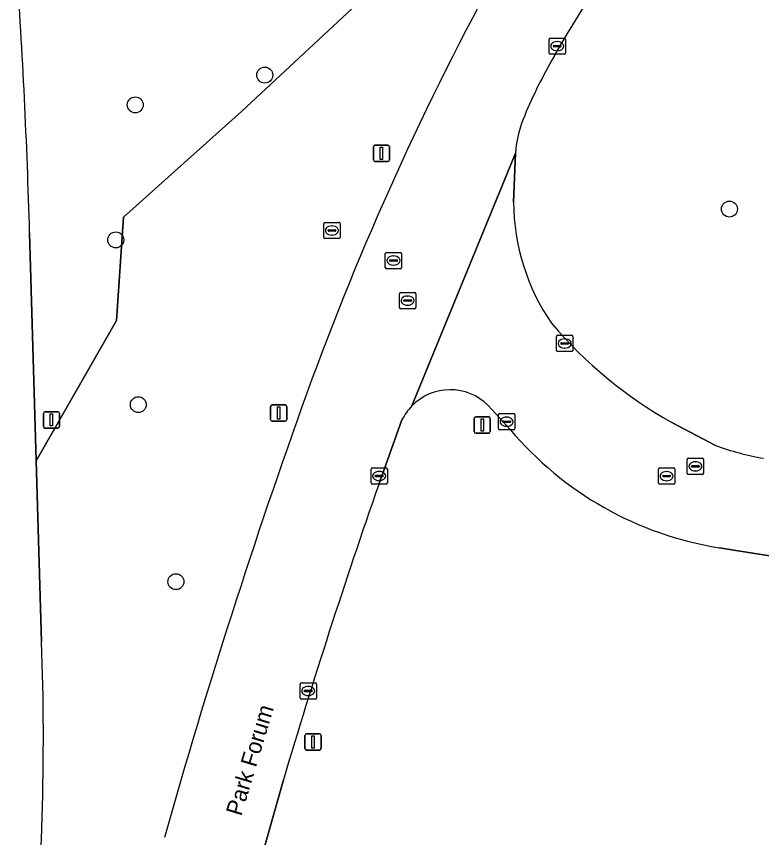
# Model space of a CAD drawing. Extents: x 154324 to 155744, y 382937 to 384188.
# Drawn here: x 155195.7 to 155241.4, y 383378 to 383428.4 of the extents above; entities that cross this region are included whole.
import ezdxf

# ---------------------------------------------------------------- set-up
doc = ezdxf.new("R2010")
doc.units = 0
for name, color, linetype in [('IMGEO_Boom', 7, 'Continuous'), ('IMGEO_Groenvoorziening', 7, 'Continuous'), ('IMGEO_Kolk', 7, 'Continuous'), ('IMGEO_Lichtmast', 7, 'Continuous'), ('IMGEO_Openbare_ruimte_label', 7, 'Continuous'), ('IMGEO_Rijbaan_lokaal_gesloten', 7, 'Continuous'), ('IMGEO_Rijbaan_lokaal_open', 7, 'Continuous'), ('IMGEO_Rijbaan_regionaal_gesloten', 7, 'Continuous'), ('IMGEO_Rioolput', 7, 'Continuous')]:
    doc.layers.add(name, color=color, linetype=linetype)

msp = doc.modelspace()

# ---------------------------------------------------------------- linework, layer by layer
at = {"layer": 'IMGEO_Boom'}
for centre in [(155210.882, 383424.797), (155202.942, 383422.968), (155239.381, 383416.578), (155201.746, 383414.682), (155203.128, 383404.578), (155205.432, 383393.717)]:
    msp.add_circle(centre, 0.489, dxfattribs=at)
at = {"layer": 'IMGEO_Groenvoorziening'}
for points in [[(155196.461, 383415.12), (155196.87, 383401.138), (155201.784, 383409.737), (155202.227, 383416.08), (155209.454, 383422.57), (155218.304, 383430.83), (155232.76, 383449.415), (155225.088, 383476.944)], [(155218.304, 383430.83), (155209.454, 383422.57), (155202.227, 383416.08), (155201.784, 383409.737), (155196.87, 383401.138), (155197.195, 383390.033)], [(155229.103, 383426.799), (155228.606, 383425.92)], [(155226.254, 383420.01), (155226.147, 383416.995)], [(155225.939, 383403.044), (155224.58, 383404.531)], [(155219.297, 383403.636), (155217.88, 383399.681)], [(155235.84, 383403.486), (155238.522, 383402.077)], [(155358.814, 383365.632), (155360.106, 383374.508), (155360.327, 383375.705), (155360.426, 383376.464), (155295.925, 383386.713), (155295.512, 383384.113), (155295.052, 383381.177), (155292.112, 383381.637), (155292.571, 383384.573), (155292.985, 383387.18), (155280.782, 383389.119), (155238.742, 383395.799)], [(155212.028, 383381.558), (155209.577, 383372.88)]]:
    msp.add_lwpolyline(points, dxfattribs=at)
for centre, radius, start, end in [((155301.885, 383383.769), 84.551, 135.8299, 149.4076), ((154803.457, 383404.194), 393.155, 1.59243, 4.00445), ((155387.616, 383342.18), 185.232, 151.172, 160.08181), ((155256.769, 383409.73), 32.485, 150.1067, 157.1969), ((155233.554, 383419.437), 7.323, 156.8139, 175.5108), ((155239.307, 383417.037), 13.16, 180.1821, 214.5883), ((155249.153, 383427.121), 27.126, 220.3266, 240.6076), ((155222.257, 383402.204), 3.288, 45.048, 135.6141), ((155598.09, 383266.96), 408.742, 160.21976, 164.23418), ((155222.261, 383402.202), 3.293, 135.6307, 154.1729), ((155242.084, 383416.64), 21.108, 220.1015, 260.889), ((155244.218, 383417.387), 16.335, 249.5942, 260.2884), ((155581.144, 383272.375), 384.925, 160.68698, 163.52201), ((155039.21, 383384.136), 158.095, 354.33172, 2.13769)]:
    msp.add_arc(centre, radius, start, end, dxfattribs=at)
at = {"layer": 'IMGEO_Kolk'}
for p, q in [((155228.393, 383427.07), (155229.245, 383427.07)), ((155228.318, 383426.144), (155228.318, 383426.996)), ((155228.577, 383426.564), (155228.577, 383426.576)), ((155229.015, 383426.527), (155228.617, 383426.527)), ((155228.62, 383426.613), (155229.018, 383426.613)), ((155228.806, 383426.85), (155228.831, 383426.85)), ((155229.061, 383426.576), (155229.061, 383426.564)), ((155229.319, 383426.996), (155229.319, 383426.144)), ((155229.245, 383426.07), (155228.393, 383426.07)), ((155228.829, 383426.29), (155228.804, 383426.29)), ((155214.499, 383414.836), (155214.499, 383415.688)), ((155214.574, 383415.762), (155215.426, 383415.762)), ((155214.987, 383415.542), (155215.012, 383415.542)), ((155215.5, 383415.688), (155215.5, 383414.836)), ((155214.758, 383415.256), (155214.758, 383415.268)), ((155215.196, 383415.219), (155214.798, 383415.219)), ((155214.801, 383415.305), (155215.199, 383415.305)), ((155215.01, 383414.982), (155214.985, 383414.982)), ((155215.242, 383415.268), (155215.242, 383415.256)), ((155215.426, 383414.762), (155214.574, 383414.762)), ((155228.774, 383407.906), (155228.774, 383408.758)), ((155228.849, 383408.832), (155229.701, 383408.832)), ((155229.076, 383408.375), (155229.474, 383408.375)), ((155229.262, 383408.612), (155229.287, 383408.612)), ((155229.775, 383408.758), (155229.775, 383407.906)), ((155229.033, 383408.326), (155229.033, 383408.338)), ((155229.471, 383408.289), (155229.073, 383408.289)), ((155229.285, 383408.052), (155229.26, 383408.052)), ((155229.517, 383408.338), (155229.517, 383408.326)), ((155229.701, 383407.832), (155228.849, 383407.832)), ((155225.214, 383403.104), (155225.214, 383403.956)), ((155225.289, 383404.03), (155226.141, 383404.03)), ((155226.215, 383403.956), (155226.215, 383403.104)), ((155225.473, 383403.524), (155225.473, 383403.536)), ((155225.911, 383403.487), (155225.513, 383403.487)), ((155225.516, 383403.573), (155225.914, 383403.573)), ((155225.702, 383403.81), (155225.727, 383403.81)), ((155225.957, 383403.536), (155225.957, 383403.524)), ((155226.141, 383403.03), (155225.289, 383403.03)), ((155225.725, 383403.25), (155225.7, 383403.25)), ((155217.399, 383399.775), (155217.399, 383400.627)), ((155217.474, 383400.701), (155218.326, 383400.701)), ((155217.887, 383400.481), (155217.912, 383400.481)), ((155218.4, 383400.627), (155218.4, 383399.775)), ((155217.658, 383400.195), (155217.658, 383400.207)), ((155218.096, 383400.158), (155217.698, 383400.158)), ((155217.701, 383400.244), (155218.099, 383400.244)), ((155217.91, 383399.921), (155217.885, 383399.921)), ((155218.142, 383400.207), (155218.142, 383400.195)), ((155218.326, 383399.701), (155217.474, 383399.701)), ((155213.049, 383386.586), (155213.049, 383387.438)), ((155213.124, 383387.512), (155213.976, 383387.512)), ((155213.537, 383387.292), (155213.562, 383387.292)), ((155214.05, 383387.438), (155214.05, 383386.586)), ((155213.308, 383387.006), (155213.308, 383387.018)), ((155213.746, 383386.969), (155213.348, 383386.969)), ((155213.351, 383387.055), (155213.749, 383387.055)), ((155213.56, 383386.732), (155213.535, 383386.732)), ((155213.792, 383387.018), (155213.792, 383387.006)), ((155213.976, 383386.512), (155213.124, 383386.512))]:
    msp.add_line(p, q, dxfattribs=at)
for points in [[(155228.393, 383427.07), (155229.245, 383427.07)], [(155228.318, 383426.144), (155228.318, 383426.996)], [(155229.319, 383426.996), (155229.319, 383426.144)], [(155229.245, 383426.07), (155228.393, 383426.07)], [(155214.499, 383414.836), (155214.499, 383415.688)], [(155214.574, 383415.762), (155215.426, 383415.762)], [(155215.5, 383415.688), (155215.5, 383414.836)], [(155215.426, 383414.762), (155214.574, 383414.762)], [(155228.774, 383407.906), (155228.774, 383408.758)], [(155228.849, 383408.832), (155229.701, 383408.832)], [(155229.775, 383408.758), (155229.775, 383407.906)], [(155229.701, 383407.832), (155228.849, 383407.832)], [(155225.214, 383403.104), (155225.214, 383403.956)], [(155225.289, 383404.03), (155226.141, 383404.03)], [(155226.215, 383403.956), (155226.215, 383403.104)], [(155226.141, 383403.03), (155225.289, 383403.03)], [(155217.399, 383399.775), (155217.399, 383400.627)], [(155217.474, 383400.701), (155218.326, 383400.701)], [(155218.4, 383400.627), (155218.4, 383399.775)], [(155218.326, 383399.701), (155217.474, 383399.701)], [(155213.049, 383386.586), (155213.049, 383387.438)], [(155213.124, 383387.512), (155213.976, 383387.512)], [(155214.05, 383387.438), (155214.05, 383386.586)], [(155213.976, 383386.512), (155213.124, 383386.512)]]:
    msp.add_lwpolyline(points, dxfattribs=at)
for centre, radius, start, end in [((155228.395, 383426.994), 0.0765, 91.552, 178.448), ((155228.395, 383426.994), 0.0765, 91.552, 178.448), ((155229.243, 383426.994), 0.0765, 1.552, 88.448), ((155229.243, 383426.994), 0.0765, 1.552, 88.448), ((155228.617, 383426.573), 0.0403, 85.8775, 175.7526), ((155228.614, 383426.563), 0.0366, 178.938, 274.7102), ((155229.018, 383426.57), 0.043, 264.8664, 352.4533), ((155229.022, 383426.575), 0.0386, 1.7309, 96.639), ((155228.395, 383426.146), 0.0765, 181.552, 268.448), ((155228.395, 383426.146), 0.0765, 181.552, 268.448), ((155229.243, 383426.146), 0.0765, 271.552, 358.448), ((155229.243, 383426.146), 0.0765, 271.552, 358.448), ((155214.576, 383415.686), 0.0765, 91.552, 178.448), ((155214.576, 383415.686), 0.0765, 91.552, 178.448), ((155215.424, 383415.686), 0.0765, 1.552, 88.448), ((155215.424, 383415.686), 0.0765, 1.552, 88.448), ((155214.798, 383415.265), 0.0403, 85.8775, 175.7526), ((155214.795, 383415.255), 0.0366, 178.938, 274.7102), ((155215.199, 383415.262), 0.043, 264.8664, 352.4533), ((155215.203, 383415.267), 0.0386, 1.7309, 96.639), ((155214.576, 383414.838), 0.0765, 181.552, 268.448), ((155214.576, 383414.838), 0.0765, 181.552, 268.448), ((155215.424, 383414.838), 0.0765, 271.552, 358.448), ((155215.424, 383414.838), 0.0765, 271.552, 358.448), ((155228.851, 383408.756), 0.0765, 91.552, 178.448), ((155228.851, 383408.756), 0.0765, 91.552, 178.448), ((155229.073, 383408.335), 0.0403, 85.8775, 175.7526), ((155229.478, 383408.337), 0.0386, 1.7309, 96.639), ((155229.699, 383408.756), 0.0765, 1.552, 88.448), ((155229.699, 383408.756), 0.0765, 1.552, 88.448), ((155228.851, 383407.908), 0.0765, 181.552, 268.448), ((155228.851, 383407.908), 0.0765, 181.552, 268.448), ((155229.07, 383408.325), 0.0366, 178.938, 274.7102), ((155229.474, 383408.332), 0.043, 264.8664, 352.4533), ((155229.699, 383407.908), 0.0765, 271.552, 358.448), ((155229.699, 383407.908), 0.0765, 271.552, 358.448), ((155225.291, 383403.954), 0.0765, 91.552, 178.448), ((155225.291, 383403.954), 0.0765, 91.552, 178.448), ((155226.139, 383403.954), 0.0765, 1.552, 88.448), ((155226.139, 383403.954), 0.0765, 1.552, 88.448), ((155225.513, 383403.533), 0.0403, 85.8775, 175.7526), ((155225.51, 383403.523), 0.0366, 178.938, 274.7102), ((155225.914, 383403.53), 0.043, 264.8664, 352.4533), ((155225.918, 383403.535), 0.0386, 1.7309, 96.639), ((155225.291, 383403.106), 0.0765, 181.552, 268.448), ((155225.291, 383403.106), 0.0765, 181.552, 268.448), ((155226.139, 383403.106), 0.0765, 271.552, 358.448), ((155226.139, 383403.106), 0.0765, 271.552, 358.448), ((155217.476, 383400.625), 0.0765, 91.552, 178.448), ((155217.476, 383400.625), 0.0765, 91.552, 178.448), ((155218.324, 383400.625), 0.0765, 1.552, 88.448), ((155218.324, 383400.625), 0.0765, 1.552, 88.448), ((155217.698, 383400.204), 0.0403, 85.8775, 175.7526), ((155217.695, 383400.194), 0.0366, 178.938, 274.7102), ((155218.099, 383400.201), 0.043, 264.8664, 352.4533), ((155218.103, 383400.206), 0.0386, 1.7309, 96.639), ((155217.476, 383399.777), 0.0765, 181.552, 268.448), ((155217.476, 383399.777), 0.0765, 181.552, 268.448), ((155218.324, 383399.777), 0.0765, 271.552, 358.448), ((155218.324, 383399.777), 0.0765, 271.552, 358.448), ((155213.126, 383387.436), 0.0765, 91.552, 178.448), ((155213.126, 383387.436), 0.0765, 91.552, 178.448), ((155213.974, 383387.436), 0.0765, 1.552, 88.448), ((155213.974, 383387.436), 0.0765, 1.552, 88.448), ((155213.348, 383387.015), 0.0403, 85.8775, 175.7526), ((155213.345, 383387.005), 0.0366, 178.938, 274.7102), ((155213.749, 383387.012), 0.043, 264.8664, 352.4533), ((155213.753, 383387.017), 0.0386, 1.7309, 96.639), ((155213.126, 383386.588), 0.0765, 181.552, 268.448), ((155213.126, 383386.588), 0.0765, 181.552, 268.448), ((155213.974, 383386.588), 0.0765, 271.552, 358.448), ((155213.974, 383386.588), 0.0765, 271.552, 358.448)]:
    msp.add_arc(centre, radius, start, end, dxfattribs=at)
for centre, major_axis, ratio, start_param, end_param in [((155228.805, 383426.57), (-0.387, 0.002), 0.722429, 4.712389, 7.853982), ((155228.83, 383426.57), (-0.39, 0.002), 0.717154, 1.570796, 4.712389), ((155214.986, 383415.262), (-0.387, 0.002), 0.722429, 4.712389, 7.853982), ((155215.011, 383415.262), (-0.39, 0.002), 0.717154, 1.570796, 4.712389), ((155229.261, 383408.332), (-0.387, 0.002), 0.722429, 4.712389, 7.853982), ((155229.286, 383408.332), (-0.39, 0.002), 0.717154, 1.570796, 4.712389), ((155225.701, 383403.53), (-0.387, 0.002), 0.722429, 4.712389, 7.853982), ((155225.726, 383403.53), (-0.39, 0.002), 0.717154, 1.570796, 4.712389), ((155217.886, 383400.201), (-0.387, 0.002), 0.722429, 4.712389, 7.853982), ((155217.911, 383400.201), (-0.39, 0.002), 0.717154, 1.570796, 4.712389), ((155213.536, 383387.012), (-0.387, 0.002), 0.722429, 4.712389, 7.853982), ((155213.561, 383387.012), (-0.39, 0.002), 0.717154, 1.570796, 4.712389)]:
    msp.add_ellipse(centre, major_axis=major_axis, ratio=ratio, start_param=start_param, end_param=end_param, dxfattribs=at)
at = {"layer": 'IMGEO_Lichtmast'}
for p, q in [((155217.642, 383420.489), (155218.432, 383420.489)), ((155218.432, 383420.489), (155217.642, 383420.489)), ((155217.542, 383419.589), (155217.542, 383420.389)), ((155217.542, 383420.389), (155217.542, 383419.589)), ((155218.532, 383420.389), (155218.532, 383419.589)), ((155218.532, 383419.589), (155218.532, 383420.389)), ((155218.432, 383419.489), (155217.642, 383419.489)), ((155217.642, 383419.489), (155218.432, 383419.489)), ((155211.237, 383403.661), (155211.237, 383404.461)), ((155211.237, 383404.461), (155211.237, 383403.661)), ((155211.337, 383404.561), (155212.127, 383404.561)), ((155212.127, 383404.561), (155211.337, 383404.561)), ((155212.227, 383404.461), (155212.227, 383403.661)), ((155212.227, 383403.661), (155212.227, 383404.461)), ((155197.305, 383403.243), (155197.305, 383404.043)), ((155197.305, 383404.043), (155197.305, 383403.243)), ((155197.405, 383404.143), (155198.195, 383404.143)), ((155198.195, 383404.143), (155197.405, 383404.143)), ((155198.295, 383404.043), (155198.295, 383403.243)), ((155198.295, 383403.243), (155198.295, 383404.043)), ((155212.127, 383403.561), (155211.337, 383403.561)), ((155211.337, 383403.561), (155212.127, 383403.561)), ((155223.726, 383402.926), (155223.726, 383403.726)), ((155223.726, 383403.726), (155223.726, 383402.926)), ((155223.826, 383403.826), (155224.616, 383403.826)), ((155224.616, 383403.826), (155223.826, 383403.826)), ((155224.716, 383403.726), (155224.716, 383402.926)), ((155224.716, 383402.926), (155224.716, 383403.726)), ((155198.195, 383403.143), (155197.405, 383403.143)), ((155197.405, 383403.143), (155198.195, 383403.143)), ((155224.616, 383402.826), (155223.826, 383402.826)), ((155223.826, 383402.826), (155224.616, 383402.826)), ((155213.342, 383383.486), (155213.342, 383384.286)), ((155213.342, 383384.286), (155213.342, 383383.486)), ((155213.442, 383384.386), (155214.232, 383384.386)), ((155214.232, 383384.386), (155213.442, 383384.386)), ((155214.332, 383384.286), (155214.332, 383383.486)), ((155214.332, 383383.486), (155214.332, 383384.286)), ((155214.232, 383383.386), (155213.442, 383383.386)), ((155213.442, 383383.386), (155214.232, 383383.386))]:
    msp.add_line(p, q, dxfattribs=at)
for points in [[(155217.962, 383420.364), (155218.112, 383420.364), (155218.112, 383419.614), (155217.962, 383419.614), (155217.962, 383420.364)], [(155211.657, 383404.436), (155211.807, 383404.436), (155211.807, 383403.686), (155211.657, 383403.686), (155211.657, 383404.436)], [(155197.725, 383404.018), (155197.875, 383404.018), (155197.875, 383403.268), (155197.725, 383403.268), (155197.725, 383404.018)], [(155224.146, 383403.701), (155224.296, 383403.701), (155224.296, 383402.951), (155224.146, 383402.951), (155224.146, 383403.701)], [(155213.762, 383384.261), (155213.912, 383384.261), (155213.912, 383383.511), (155213.762, 383383.511), (155213.762, 383384.261)]]:
    msp.add_lwpolyline(points, dxfattribs=at)
for centre, start, end in [((155217.642, 383420.389), 90, 180), ((155217.642, 383420.389), 90, 180), ((155218.432, 383420.389), 0, 90), ((155218.432, 383420.389), 360, 90), ((155217.642, 383419.589), 180, 270), ((155217.642, 383419.589), 180, 270), ((155218.432, 383419.589), 270, 0), ((155218.432, 383419.589), 270, 0), ((155211.337, 383404.461), 90, 180), ((155211.337, 383404.461), 90, 180), ((155212.127, 383404.461), 0, 90), ((155212.127, 383404.461), 360, 90), ((155197.405, 383404.043), 90, 180), ((155197.405, 383404.043), 90, 180), ((155198.195, 383404.043), 0, 90), ((155198.195, 383404.043), 360, 90), ((155211.337, 383403.661), 180, 270), ((155211.337, 383403.661), 180, 270), ((155212.127, 383403.661), 270, 0), ((155212.127, 383403.661), 270, 0), ((155223.826, 383403.726), 90, 180), ((155223.826, 383403.726), 90, 180), ((155224.616, 383403.726), 0, 90), ((155224.616, 383403.726), 360, 90), ((155197.405, 383403.243), 180, 270), ((155197.405, 383403.243), 180, 270), ((155198.195, 383403.243), 270, 0), ((155198.195, 383403.243), 270, 0), ((155223.826, 383402.926), 180, 270), ((155223.826, 383402.926), 180, 270), ((155224.616, 383402.926), 270, 0), ((155224.616, 383402.926), 270, 0), ((155213.442, 383384.286), 90, 180), ((155213.442, 383384.286), 90, 180), ((155214.232, 383384.286), 0, 90), ((155214.232, 383384.286), 360, 90), ((155213.442, 383383.486), 180, 270), ((155213.442, 383383.486), 180, 270), ((155214.232, 383383.486), 270, 0), ((155214.232, 383383.486), 270, 0)]:
    msp.add_arc(centre, 0.1, start, end, dxfattribs=at)
at = {"layer": 'IMGEO_Rijbaan_lokaal_gesloten'}
for points in [[(155226.147, 383416.995), (155226.254, 383420.01), (155219.907, 383404.504)], [(155224.58, 383404.531), (155225.939, 383403.044)], [(155238.522, 383402.077), (155235.84, 383403.486)], [(155238.742, 383395.799), (155280.782, 383389.119), (155292.985, 383387.18), (155295.925, 383386.713), (155360.426, 383376.464), (155366.366, 383375.502), (155368.377, 383375.447), (155369.374, 383375.593), (155371.331, 383376.087), (155374.899, 383377.537), (155376.703, 383378.478), (155378.429, 383379.542)]]:
    msp.add_lwpolyline(points, dxfattribs=at)
for centre, radius, start, end in [((155239.307, 383417.037), 13.16, 180.1821, 214.5883), ((155249.153, 383427.121), 27.126, 220.3266, 240.6076), ((155222.257, 383402.204), 3.288, 45.048, 135.6141), ((155242.084, 383416.64), 21.108, 220.1015, 260.889), ((155244.218, 383417.387), 16.335, 249.5942, 260.2884)]:
    msp.add_arc(centre, radius, start, end, dxfattribs=at)
at = {"layer": 'IMGEO_Rijbaan_lokaal_open'}
for points in [[(155228.606, 383425.92), (155229.103, 383426.799)], [(155219.907, 383404.504), (155226.254, 383420.01)], [(155217.88, 383399.681), (155219.297, 383403.636)], [(155209.577, 383372.88), (155212.028, 383381.558)]]:
    msp.add_lwpolyline(points, dxfattribs=at)
for centre, radius, start, end in [((155301.885, 383383.769), 84.551, 135.8299, 149.4076), ((155387.616, 383342.18), 185.232, 151.172, 160.08181), ((155256.769, 383409.73), 32.485, 150.1067, 157.1969), ((155233.554, 383419.437), 7.323, 156.8139, 175.5108), ((155598.09, 383266.96), 408.742, 160.21976, 164.23418), ((155222.261, 383402.202), 3.293, 135.6307, 154.1729), ((155581.144, 383272.375), 384.925, 160.68698, 163.52201)]:
    msp.add_arc(centre, radius, start, end, dxfattribs=at)
at = {"layer": 'IMGEO_Rijbaan_regionaal_gesloten'}
msp.add_lwpolyline([(155197.195, 383390.033), (155196.87, 383401.138), (155196.461, 383415.12)], dxfattribs=at)
for centre, radius, start, end in [((154803.457, 383404.194), 393.155, 1.59243, 4.00445), ((155039.21, 383384.136), 158.095, 354.33172, 2.13769)]:
    msp.add_arc(centre, radius, start, end, dxfattribs=at)
at = {"layer": 'IMGEO_Rioolput'}
for p, q in [((155218.35, 383413.918), (155219.202, 383413.918)), ((155218.275, 383412.992), (155218.275, 383413.844)), ((155218.534, 383413.412), (155218.534, 383413.424)), ((155218.577, 383413.461), (155218.975, 383413.461)), ((155218.763, 383413.698), (155218.788, 383413.698)), ((155219.018, 383413.424), (155219.018, 383413.412)), ((155219.276, 383413.844), (155219.276, 383412.992)), ((155219.202, 383412.918), (155218.35, 383412.918)), ((155218.972, 383413.375), (155218.574, 383413.375)), ((155218.786, 383413.138), (155218.761, 383413.138)), ((155219.22, 383411.459), (155220.072, 383411.459)), ((155219.145, 383410.533), (155219.145, 383411.385)), ((155219.404, 383410.953), (155219.404, 383410.965)), ((155219.842, 383410.916), (155219.444, 383410.916)), ((155219.447, 383411.002), (155219.845, 383411.002)), ((155219.633, 383411.239), (155219.658, 383411.239)), ((155219.888, 383410.965), (155219.888, 383410.953)), ((155220.146, 383411.385), (155220.146, 383410.533)), ((155220.072, 383410.459), (155219.22, 383410.459)), ((155219.656, 383410.679), (155219.631, 383410.679)), ((155236.791, 383400.368), (155236.791, 383401.22)), ((155236.866, 383401.294), (155237.718, 383401.294)), ((155237.093, 383400.837), (155237.491, 383400.837)), ((155237.279, 383401.074), (155237.304, 383401.074)), ((155237.792, 383401.22), (155237.792, 383400.368)), ((155235.026, 383399.767), (155235.026, 383400.619)), ((155235.101, 383400.693), (155235.953, 383400.693)), ((155235.514, 383400.473), (155235.539, 383400.473)), ((155236.027, 383400.619), (155236.027, 383399.767)), ((155237.05, 383400.788), (155237.05, 383400.8)), ((155237.488, 383400.751), (155237.09, 383400.751)), ((155237.302, 383400.514), (155237.277, 383400.514)), ((155237.534, 383400.8), (155237.534, 383400.788)), ((155235.285, 383400.187), (155235.285, 383400.199)), ((155235.723, 383400.15), (155235.325, 383400.15)), ((155235.328, 383400.236), (155235.726, 383400.236)), ((155235.537, 383399.913), (155235.512, 383399.913)), ((155235.769, 383400.199), (155235.769, 383400.187)), ((155237.718, 383400.294), (155236.866, 383400.294)), ((155235.953, 383399.693), (155235.101, 383399.693))]:
    msp.add_line(p, q, dxfattribs=at)
for points in [[(155218.35, 383413.918), (155219.202, 383413.918)], [(155218.275, 383412.992), (155218.275, 383413.844)], [(155219.276, 383413.844), (155219.276, 383412.992)], [(155219.202, 383412.918), (155218.35, 383412.918)], [(155219.22, 383411.459), (155220.072, 383411.459)], [(155219.145, 383410.533), (155219.145, 383411.385)], [(155220.146, 383411.385), (155220.146, 383410.533)], [(155220.072, 383410.459), (155219.22, 383410.459)], [(155236.791, 383400.368), (155236.791, 383401.22)], [(155236.866, 383401.294), (155237.718, 383401.294)], [(155237.792, 383401.22), (155237.792, 383400.368)], [(155235.026, 383399.767), (155235.026, 383400.619)], [(155235.101, 383400.693), (155235.953, 383400.693)], [(155236.027, 383400.619), (155236.027, 383399.767)], [(155237.718, 383400.294), (155236.866, 383400.294)], [(155235.953, 383399.693), (155235.101, 383399.693)]]:
    msp.add_lwpolyline(points, dxfattribs=at)
for centre, radius, start, end in [((155218.352, 383413.842), 0.0765, 91.552, 178.448), ((155218.352, 383413.842), 0.0765, 91.552, 178.448), ((155219.2, 383413.842), 0.0765, 1.552, 88.448), ((155219.2, 383413.842), 0.0765, 1.552, 88.448), ((155218.574, 383413.421), 0.0403, 85.8775, 175.7526), ((155218.571, 383413.411), 0.0366, 178.938, 274.7102), ((155218.975, 383413.418), 0.043, 264.8664, 352.4533), ((155218.979, 383413.423), 0.0386, 1.7309, 96.639), ((155218.352, 383412.994), 0.0765, 181.552, 268.448), ((155218.352, 383412.994), 0.0765, 181.552, 268.448), ((155219.2, 383412.994), 0.0765, 271.552, 358.448), ((155219.2, 383412.994), 0.0765, 271.552, 358.448), ((155219.222, 383411.383), 0.0765, 91.552, 178.448), ((155219.222, 383411.383), 0.0765, 91.552, 178.448), ((155220.07, 383411.383), 0.0765, 1.552, 88.448), ((155220.07, 383411.383), 0.0765, 1.552, 88.448), ((155219.444, 383410.962), 0.0403, 85.8775, 175.7526), ((155219.441, 383410.952), 0.0366, 178.938, 274.7102), ((155219.845, 383410.959), 0.043, 264.8664, 352.4533), ((155219.849, 383410.964), 0.0386, 1.7309, 96.639), ((155219.222, 383410.535), 0.0765, 181.552, 268.448), ((155219.222, 383410.535), 0.0765, 181.552, 268.448), ((155220.07, 383410.535), 0.0765, 271.552, 358.448), ((155220.07, 383410.535), 0.0765, 271.552, 358.448), ((155236.868, 383401.218), 0.0765, 91.552, 178.448), ((155236.868, 383401.218), 0.0765, 91.552, 178.448), ((155237.09, 383400.797), 0.0403, 85.8775, 175.7526), ((155237.495, 383400.799), 0.0386, 1.7309, 96.639), ((155237.716, 383401.218), 0.0765, 1.552, 88.448), ((155237.716, 383401.218), 0.0765, 1.552, 88.448), ((155235.103, 383400.617), 0.0765, 91.552, 178.448), ((155235.103, 383400.617), 0.0765, 91.552, 178.448), ((155235.951, 383400.617), 0.0765, 1.552, 88.448), ((155235.951, 383400.617), 0.0765, 1.552, 88.448), ((155236.868, 383400.37), 0.0765, 181.552, 268.448), ((155236.868, 383400.37), 0.0765, 181.552, 268.448), ((155237.087, 383400.787), 0.0366, 178.938, 274.7102), ((155237.491, 383400.794), 0.043, 264.8664, 352.4533), ((155237.716, 383400.37), 0.0765, 271.552, 358.448), ((155237.716, 383400.37), 0.0765, 271.552, 358.448), ((155235.325, 383400.196), 0.0403, 85.8775, 175.7526), ((155235.322, 383400.186), 0.0366, 178.938, 274.7102), ((155235.726, 383400.193), 0.043, 264.8664, 352.4533), ((155235.73, 383400.198), 0.0386, 1.7309, 96.639), ((155235.103, 383399.769), 0.0765, 181.552, 268.448), ((155235.103, 383399.769), 0.0765, 181.552, 268.448), ((155235.951, 383399.769), 0.0765, 271.552, 358.448), ((155235.951, 383399.769), 0.0765, 271.552, 358.448)]:
    msp.add_arc(centre, radius, start, end, dxfattribs=at)
for centre, major_axis, ratio, start_param, end_param in [((155218.762, 383413.418), (-0.387, 0.002), 0.722429, 4.712389, 7.853982), ((155218.787, 383413.418), (-0.39, 0.002), 0.717154, 1.570796, 4.712389), ((155219.632, 383410.959), (-0.387, 0.002), 0.722429, 4.712389, 7.853982), ((155219.657, 383410.959), (-0.39, 0.002), 0.717154, 1.570796, 4.712389), ((155237.278, 383400.794), (-0.387, 0.002), 0.722429, 4.712389, 7.853982), ((155237.303, 383400.794), (-0.39, 0.002), 0.717154, 1.570796, 4.712389), ((155235.513, 383400.193), (-0.387, 0.002), 0.722429, 4.712389, 7.853982), ((155235.538, 383400.193), (-0.39, 0.002), 0.717154, 1.570796, 4.712389)]:
    msp.add_ellipse(centre, major_axis=major_axis, ratio=ratio, start_param=start_param, end_param=end_param, dxfattribs=at)

# ---------------------------------------------------------------- texts
at = {"layer": 'IMGEO_Openbare_ruimte_label'}
msp.add_text('Park Forum', height=1, rotation=73.2678, dxfattribs=at).set_placement((155209.439, 383379.293))

doc.saveas('drawing.dxf')
